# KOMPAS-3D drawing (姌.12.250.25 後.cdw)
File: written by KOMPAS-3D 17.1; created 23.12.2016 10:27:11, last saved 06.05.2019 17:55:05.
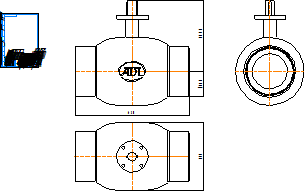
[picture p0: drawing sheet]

Sheet 1: A4, portrait

Title block, sheet 1: name: КШ.12.250.25 сс; material: Внимание! Данный продукт является объектом авторского права ООО «Торговый Дом АДЛ». / Запрещается изменение, копирование, распространение / (в том числе путем копирования на другие сайты и ресурсы в Интернете) / или любое иное использование информации и объектов без предварительного / согласия правообладателя (ООО «Торговый Дом АДЛ»).; sheets: 1; organisation: ООО "Торговый дом АДЛ"; sheet format: A4; stored path: C:\Users\tra\Desktop\2д чертежи\Шаровые краны БИВАЛ\КШ_Бивал_серия_11_12\KOMPAS_2D\КШ.12.250.25 сс.cdw

Views: Вид 1, Проекционный вид 2, Проекционный вид 3
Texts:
  Klimkovich
  ADL
Dimensions and other numbers on the sheet: 630; 389,2; 136,5; 377; 1:1; 1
